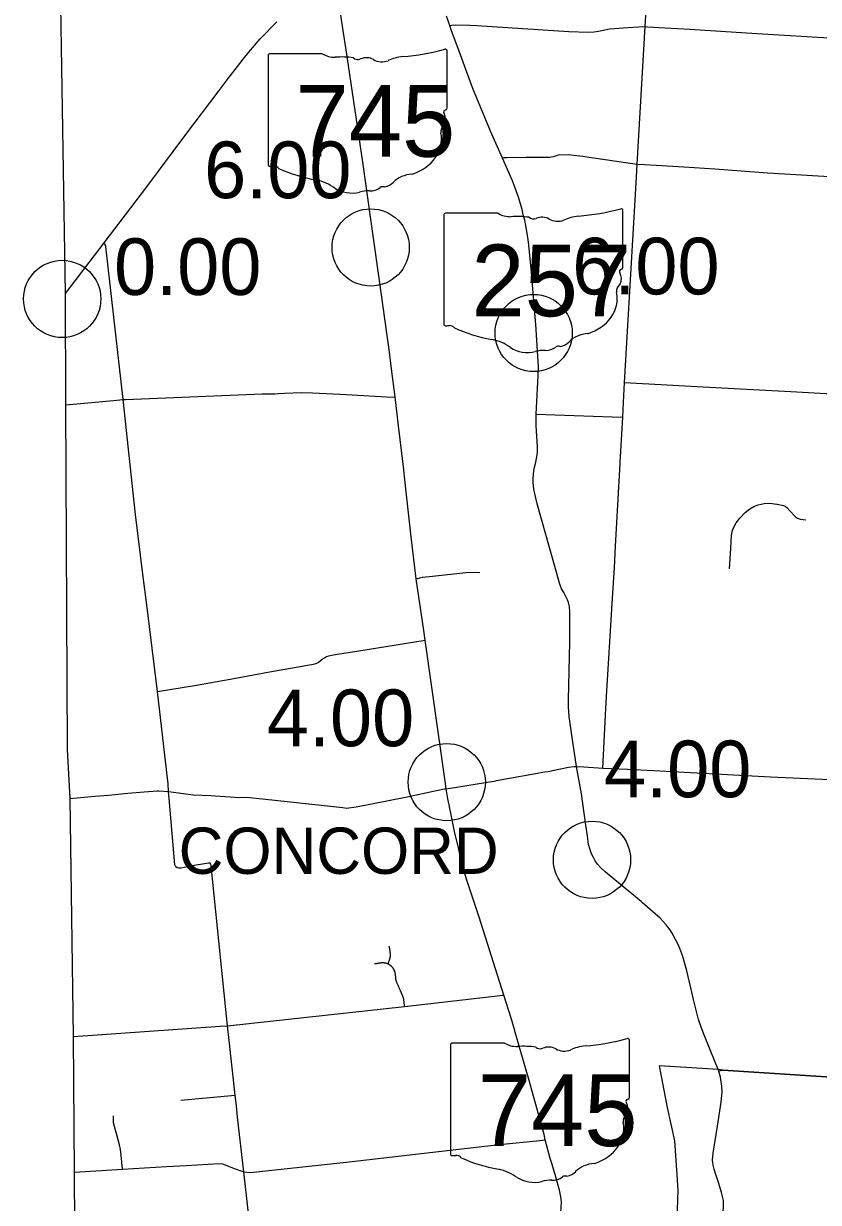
# Model space of a CAD drawing. Extents: x 1597222 to 1925846, y 496284 to 911751.
# Drawn here: x 1780072 to 1795517, y 792512 to 815408 of the extents above; entities that cross this region are included whole.
import ezdxf

# ---------------------------------------------------------------- set-up
doc = ezdxf.new("R2010")
doc.units = 0
for name, color, linetype in [('Default', 7, 'Continuous'), ('GM_X_County', 7, 'Continuous'), ('GM_X_County_Road', 7, 'Continuous'), ('GM_X_State_Route', 7, 'Continuous'), ('GM_X_State_Shield', 7, 'Continuous'), ('GM_X_Township', 7, 'Continuous'), ('GM_X_Township_Road', 7, 'Continuous'), ('GM_X_Township_Text', 7, 'Continuous'), ('GM_X_US_Route', 7, 'Continuous')]:
    doc.layers.add(name, color=color, linetype=linetype)

msp = doc.modelspace()

# ---------------------------------------------------------------- linework, layer by layer
at = {"layer": 'Default'}
for centre in [(1786817, 811060), (1780822, 810060), (1780822, 810060), (1789983, 809398), (1788295, 800675), (1791118, 799166)]:
    msp.add_circle(centre, 750, dxfattribs=at)
at = {"layer": 'GM_X_County'}
msp.add_lwpolyline([(1781083, 789921), (1781062, 793102), (1781040, 795733), (1780979, 800357), (1780927, 801312), (1780895, 808002), (1780889, 810163), (1780755, 818148)], dxfattribs=at)
at = {"layer": 'GM_X_County_Road'}
for points in [[(1791713, 807764), (1791713, 807764), (1791727, 808049), (1791747, 808435), (1791981, 812422), (1791996, 812680), (1792152, 815352), (1792421, 819851), (1792558, 822011)], [(1782890, 800490), (1782881, 800644), (1782856, 800863), (1782676, 802437), (1782464, 804119), (1782395, 804661), (1782246, 805871), (1782006, 808105), (1781669, 811078), (1781659, 811109), (1781650, 811131), (1781636, 811151)], [(1780895, 808002), (1781819, 808088), (1782006, 808105), (1782052, 808109), (1784707, 808216), (1784962, 808220), (1785026, 808223), (1785143, 808231), (1785474, 808240), (1785685, 808234), (1786347, 808204), (1787231, 808155), (1787289, 808159)], [(1791747, 808435), (1793395, 808348), (1794980, 808260), (1797031, 808146), (1797107, 808141), (1797153, 808138)], [(1790033, 807825), (1791509, 807773), (1791713, 807764)], [(1791328, 800949), (1791359, 801588), (1791381, 801980), (1791400, 802336), (1791517, 804248), (1791555, 804839), (1791576, 805255), (1791663, 806861), (1791666, 806898), (1791673, 806996), (1791713, 807764)], [(1790259, 800884), (1790662, 800965), (1790767, 800980), (1790816, 800981)], [(1790816, 800981), (1790957, 800973), (1791328, 800949), (1791805, 800926), (1792317, 800900), (1794586, 800781), (1795455, 800738), (1796520, 800687)], [(1788284, 800545), (1789248, 800701)], [(1789248, 800701), (1789260, 800704), (1790202, 800872), (1790259, 800884)], [(1780979, 800357), (1781251, 800385), (1781456, 800401), (1781721, 800423), (1782095, 800460), (1782415, 800484), (1782676, 800509), (1782703, 800508), (1782890, 800490), (1783080, 800464), (1783370, 800430), (1783710, 800417), (1784177, 800386), (1784465, 800376), (1784774, 800347), (1786277, 800180), (1786348, 800171), (1786537, 800193), (1787491, 800386), (1788093, 800511), (1788252, 800542), (1788284, 800545)], [(1784231, 794169), (1784213, 794320), (1784208, 794381), (1784184, 794592), (1784065, 795658), (1784036, 795945), (1783745, 798796), (1783719, 799058), (1783710, 799082), (1783697, 799100), (1783664, 799103), (1783307, 799040), (1783135, 799003), (1783086, 799003), (1783057, 799012), (1783029, 799032), (1783012, 799071), (1782957, 799680), (1782900, 800360), (1782890, 800490)], [(1784354, 793107), (1784231, 794169)]]:
    msp.add_lwpolyline(points, dxfattribs=at)
at = {"layer": 'GM_X_State_Route'}
for points in [[(1790208, 793730), (1790185, 793831), (1789883, 794924), (1789691, 795593), (1789552, 796074), (1789406, 796539), (1788925, 798054), (1788685, 798770), (1788593, 799061), (1788574, 799137), (1788559, 799211), (1788513, 799432), (1788454, 799683), (1788376, 800070), (1788357, 800160), (1788339, 800233), (1788316, 800352), (1788284, 800545), (1788263, 800693), (1787872, 803431), (1787846, 803622), (1787700, 804624), (1787601, 805437), (1787484, 806491), (1787451, 806800), (1787357, 807594), (1787289, 808159), (1787220, 808700), (1787174, 809078), (1787137, 809350), (1786980, 810466), (1786873, 811238), (1786667, 812717), (1786361, 814768), (1786233, 815611)], [(1789933, 810648), (1789882, 811163), (1789857, 811335), (1789809, 811591), (1789782, 811691), (1789760, 811794), (1789687, 812036), (1789570, 812353), (1789380, 812793), (1789145, 813319), (1788800, 814150), (1788666, 814519), (1788535, 814873), (1788387, 815268), (1788352, 815370), (1788288, 815554)], [(1789995, 809943), (1789934, 810642), (1789933, 810648)], [(1790677, 804093), (1790675, 804108), (1790660, 804164), (1790640, 804215), (1790609, 804281), (1790568, 804355), (1790526, 804429), (1790485, 804541), (1790432, 804726), (1790051, 806083), (1789985, 806362), (1789973, 806499), (1789971, 806567), (1789977, 806663), (1789996, 806768), (1790026, 806892), (1790053, 807030), (1790058, 807087), (1790058, 807184), (1790033, 807604), (1790033, 807825), (1790068, 808566), (1790079, 808738), (1790028, 809565), (1789995, 809943)], [(1790684, 803416), (1790687, 803933), (1790683, 804011), (1790681, 804061), (1790677, 804093)], [(1790816, 800981), (1790725, 801587), (1790674, 801951), (1790662, 802137), (1790662, 802272), (1790684, 803396), (1790684, 803416)], [(1792099, 798333), (1792069, 798359), (1791739, 798628), (1791453, 798865), (1791371, 798933), (1791282, 799017), (1791224, 799083), (1791180, 799145), (1791143, 799214), (1791110, 799281), (1791078, 799363), (1791051, 799466), (1791032, 799632), (1791000, 799840), (1790910, 800451), (1790816, 800981)], [(1793626, 794462), (1793626, 794462), (1793641, 794594), (1793644, 794648), (1793641, 794771), (1793623, 794897), (1793613, 794945), (1793580, 795059), (1793566, 795094), (1793498, 795270), (1793303, 795745), (1793237, 795913), (1793188, 796062), (1793091, 796453), (1793034, 796681), (1792957, 797013), (1792916, 797174), (1792881, 797288), (1792802, 797495), (1792672, 797742), (1792629, 797811), (1792556, 797903), (1792444, 798033), (1792099, 798333)], [(1793540, 791608), (1793549, 791942), (1793553, 792041), (1793562, 792113), (1793568, 792137), (1793585, 792183), (1793636, 792281), (1793653, 792321), (1793664, 792356), (1793672, 792401), (1793674, 792449), (1793673, 792501), (1793669, 792548), (1793654, 792626), (1793633, 792702), (1793579, 792877), (1793527, 793036), (1793489, 793158), (1793469, 793235), (1793462, 793288), (1793461, 793331), (1793468, 793471), (1793556, 793991), (1793626, 794462)], [(1790307, 793367), (1790208, 793730)], [(1790432, 790335), (1790390, 790706), (1790390, 790920), (1790399, 791128), (1790496, 792123), (1790514, 792320), (1790520, 792424), (1790521, 792501), (1790516, 792584), (1790507, 792652), (1790487, 792748), (1790462, 792838), (1790399, 793056), (1790334, 793268), (1790307, 793367)]]:
    msp.add_lwpolyline(points, dxfattribs=at)
at = {"layer": 'GM_X_State_Shield'}
for p, q in [((1788303, 813769), (1788303, 814875)), ((1788303, 813769), (1788303, 814875)), ((1784823, 814786), (1784823, 812673)), ((1784823, 814786), (1784823, 812673)), ((1785876, 814822), (1784857, 814822)), ((1785876, 814822), (1784857, 814822)), ((1788303, 813769), (1788303, 813769)), ((1788303, 813769), (1788303, 813769)), ((1788237, 811688), (1788237, 809575)), ((1788237, 811688), (1788237, 809575)), ((1789291, 811725), (1788271, 811725)), ((1789291, 811725), (1788271, 811725)), ((1791717, 810671), (1791717, 811777)), ((1791717, 810671), (1791717, 811777)), ((1791717, 810672), (1791717, 810671)), ((1791717, 810672), (1791717, 810671)), ((1791845, 794554), (1791845, 795660)), ((1791845, 794554), (1791845, 795660)), ((1788365, 795571), (1788365, 793458)), ((1788365, 795571), (1788365, 793458)), ((1789418, 795607), (1788399, 795607)), ((1789418, 795607), (1788399, 795607)), ((1791845, 794555), (1791845, 794554)), ((1791845, 794555), (1791845, 794554))]:
    msp.add_line(p, q, dxfattribs=at)
for centre, major_axis, start_param, end_param in [((1787063, 817703), (3691, 0), 4.814394, 5.042369), ((1787063, 817703), (3691, 0), 4.814394, 5.042369), ((1788264, 814879), (38.7, 0), 6.141152, 7.989035), ((1788264, 814879), (38.7, 0), 6.141152, 7.989035), ((1784863, 814790), (40.3, 0), 1.712693, 3.28349), ((1784863, 814790), (40.3, 0), 1.712693, 3.28349), ((1786119, 815068), (391, 0), 4.042523, 4.731795), ((1786119, 815068), (391, 0), 4.042523, 4.731795), ((1786249, 813636), (1404, 0), 1.404758, 1.657858), ((1786249, 813636), (1404, 0), 1.404758, 1.657858), ((1786567, 814801), (113, 0), 3.836095, 5.185415), ((1786567, 814801), (113, 0), 3.836095, 5.185415), ((1786733, 814557), (235, 0), 0.950623, 2.079405), ((1786733, 814557), (235, 0), 0.950623, 2.079405), ((1787036, 814892), (282, 0), 4.081561, 5.145723), ((1787036, 814892), (282, 0), 4.081561, 5.145723), ((1787534, 814177), (743, 0), 1.699011, 2.107814), ((1787534, 814177), (743, 0), 1.699011, 2.107814), ((1788294, 813688), (60, 0), 1.883978, 3.671073), ((1788294, 813688), (60, 0), 1.883978, 3.671073), ((1788262, 813765), (41.5, 0), 5.05454, 6.418171), ((1788262, 813765), (41.5, 0), 5.05454, 6.418171), ((1787913, 813548), (360, 0), 5.934695, 6.695948), ((1787913, 813548), (360, 0), 5.934695, 6.695948), ((1787270, 813166), (923, 0), 5.101752, 6.440018), ((1787270, 813166), (923, 0), 5.101752, 6.440018), ((1788442, 813306), (262, 0), 2.387724, 3.262537), ((1788442, 813306), (262, 0), 2.387724, 3.262537), ((1784863, 812668), (40.7, 0), 3.00124, 4.508301), ((1784863, 812668), (40.7, 0), 3.00124, 4.508301), ((1784869, 812884), (310, 0), 4.665946, 4.897461), ((1784869, 812884), (310, 0), 4.665946, 4.897461), ((1784933, 812551), (112, 0), 0.519207, 1.627899), ((1784933, 812551), (112, 0), 0.519207, 1.627899), ((1786346, 814449), (2665, 0), 4.195997, 4.488961), ((1786346, 814449), (2665, 0), 4.195997, 4.488961), ((1785551, 811723), (834, 0), 0.823519, 1.323587), ((1785551, 811723), (834, 0), 0.823519, 1.323587), ((1787659, 812079), (506, 0), 1.647645, 2.488434), ((1787659, 812079), (506, 0), 1.647645, 2.488434), ((1786453, 812540), (529, 0), 4.026481, 4.996735), ((1786453, 812540), (529, 0), 4.026481, 4.996735), ((1786759, 811810), (435, 0), 1.495662, 1.94098), ((1786759, 811810), (435, 0), 1.495662, 1.94098), ((1786797, 812382), (282, 0), 4.691044, 5.507374), ((1786797, 812382), (282, 0), 4.691044, 5.507374), ((1787053, 812177), (79.4, 0), 1.147584, 2.315152), ((1787053, 812177), (79.4, 0), 1.147584, 2.315152), ((1787019, 812468), (298, 0), 4.937069, 5.64225), ((1787019, 812468), (298, 0), 4.937069, 5.64225), ((1788277, 811693), (40.3, 0), 1.712693, 3.28349), ((1788277, 811693), (40.3, 0), 1.712693, 3.28349), ((1789533, 811970), (391, 0), 4.042523, 4.731795), ((1789533, 811970), (391, 0), 4.042523, 4.731795), ((1789663, 810538), (1404, 0), 1.404758, 1.657858), ((1789663, 810538), (1404, 0), 1.404758, 1.657858), ((1790948, 811079), (743, 0), 1.699011, 2.107814), ((1790948, 811079), (743, 0), 1.699011, 2.107814), ((1790478, 814606), (3691, 0), 4.814394, 5.042369), ((1790478, 814606), (3691, 0), 4.814394, 5.042369), ((1791679, 811782), (38.7, 0), 6.141152, 7.989035), ((1791679, 811782), (38.7, 0), 6.141152, 7.989035), ((1789982, 811704), (113, 0), 3.836095, 5.185415), ((1789982, 811704), (113, 0), 3.836095, 5.185415), ((1790147, 811459), (235, 0), 0.950623, 2.079405), ((1790147, 811459), (235, 0), 0.950623, 2.079405), ((1790450, 811794), (282, 0), 4.081561, 5.145723), ((1790450, 811794), (282, 0), 4.081561, 5.145723), ((1791708, 810590), (60, 0), 1.883978, 3.671073), ((1791708, 810590), (60, 0), 1.883978, 3.671073), ((1791327, 810451), (360, 0), 5.934695, 6.695948), ((1791327, 810451), (360, 0), 5.934695, 6.695948), ((1791676, 810667), (41.5, 0), 5.05454, 6.418171), ((1791676, 810667), (41.5, 0), 5.05454, 6.418171), ((1791856, 810209), (262, 0), 2.387724, 3.262537), ((1791856, 810209), (262, 0), 2.387724, 3.262537), ((1790684, 810068), (923, 0), 5.101752, 6.440018), ((1790684, 810068), (923, 0), 5.101752, 6.440018), ((1788277, 809570), (40.7, 0), 3.00124, 4.508301), ((1788277, 809570), (40.7, 0), 3.00124, 4.508301), ((1788283, 809787), (310, 0), 4.665946, 4.897461), ((1788283, 809787), (310, 0), 4.665946, 4.897461), ((1788347, 809453), (112, 0), 0.519207, 1.627899), ((1788347, 809453), (112, 0), 0.519207, 1.627899), ((1789760, 811352), (2665, 0), 4.195997, 4.488961), ((1789760, 811352), (2665, 0), 4.195997, 4.488961), ((1791074, 808982), (506, 0), 1.647645, 2.488434), ((1791074, 808982), (506, 0), 1.647645, 2.488434), ((1788965, 808626), (834, 0), 0.823519, 1.323587), ((1788965, 808626), (834, 0), 0.823519, 1.323587), ((1790467, 809080), (79.4, 0), 1.147584, 2.315152), ((1790467, 809080), (79.4, 0), 1.147584, 2.315152), ((1790433, 809370), (298, 0), 4.937069, 5.64225), ((1790433, 809370), (298, 0), 4.937069, 5.64225), ((1789867, 809443), (529, 0), 4.026481, 4.996735), ((1789867, 809443), (529, 0), 4.026481, 4.996735), ((1790173, 808712), (435, 0), 1.495662, 1.94098), ((1790173, 808712), (435, 0), 1.495662, 1.94098), ((1790212, 809284), (282, 0), 4.691044, 5.507374), ((1790212, 809284), (282, 0), 4.691044, 5.507374), ((1790605, 798489), (3691, 0), 4.814394, 5.042369), ((1790605, 798489), (3691, 0), 4.814394, 5.042369), ((1791806, 795664), (38.7, 0), 6.141152, 7.989035), ((1791806, 795664), (38.7, 0), 6.141152, 7.989035), ((1788404, 795576), (40.3, 0), 1.712693, 3.28349), ((1788404, 795576), (40.3, 0), 1.712693, 3.28349), ((1789661, 795853), (391, 0), 4.042523, 4.731795), ((1789661, 795853), (391, 0), 4.042523, 4.731795), ((1789791, 794421), (1404, 0), 1.404758, 1.657858), ((1789791, 794421), (1404, 0), 1.404758, 1.657858), ((1790109, 795587), (113, 0), 3.836095, 5.185415), ((1790109, 795587), (113, 0), 3.836095, 5.185415), ((1790275, 795342), (235, 0), 0.950623, 2.079405), ((1790275, 795342), (235, 0), 0.950623, 2.079405), ((1790578, 795677), (282, 0), 4.081561, 5.145723), ((1790578, 795677), (282, 0), 4.081561, 5.145723), ((1791076, 794962), (743, 0), 1.699011, 2.107814), ((1791076, 794962), (743, 0), 1.699011, 2.107814), ((1791836, 794473), (60, 0), 1.883978, 3.671073), ((1791836, 794473), (60, 0), 1.883978, 3.671073), ((1791804, 794550), (41.5, 0), 5.05454, 6.418171), ((1791804, 794550), (41.5, 0), 5.05454, 6.418171), ((1791455, 794333), (360, 0), 5.934695, 6.695948), ((1791455, 794333), (360, 0), 5.934695, 6.695948), ((1790812, 793951), (923, 0), 5.101752, 6.440018), ((1790812, 793951), (923, 0), 5.101752, 6.440018), ((1791984, 794092), (262, 0), 2.387724, 3.262537), ((1791984, 794092), (262, 0), 2.387724, 3.262537), ((1788405, 793453), (40.7, 0), 3.00124, 4.508301), ((1788405, 793453), (40.7, 0), 3.00124, 4.508301), ((1788411, 793669), (310, 0), 4.665946, 4.897461), ((1788411, 793669), (310, 0), 4.665946, 4.897461), ((1788475, 793336), (112, 0), 0.519207, 1.627899), ((1788475, 793336), (112, 0), 0.519207, 1.627899), ((1789888, 795235), (2665, 0), 4.195997, 4.488961), ((1789888, 795235), (2665, 0), 4.195997, 4.488961), ((1789093, 792508), (834, 0), 0.823519, 1.323587), ((1789093, 792508), (834, 0), 0.823519, 1.323587), ((1791201, 792864), (506, 0), 1.647645, 2.488434), ((1791201, 792864), (506, 0), 1.647645, 2.488434), ((1789995, 793325), (529, 0), 4.026481, 4.996735), ((1789995, 793325), (529, 0), 4.026481, 4.996735), ((1790301, 792595), (435, 0), 1.495662, 1.94098), ((1790301, 792595), (435, 0), 1.495662, 1.94098), ((1790339, 793167), (282, 0), 4.691044, 5.507374), ((1790339, 793167), (282, 0), 4.691044, 5.507374), ((1790595, 792962), (79.4, 0), 1.147584, 2.315152), ((1790595, 792962), (79.4, 0), 1.147584, 2.315152), ((1790561, 793253), (298, 0), 4.937069, 5.64225), ((1790561, 793253), (298, 0), 4.937069, 5.64225)]:
    msp.add_ellipse(centre, major_axis=major_axis, ratio=0.8, start_param=start_param, end_param=end_param, dxfattribs=at)
at = {"layer": 'GM_X_Township'}
msp.add_lwpolyline([(1797746, 818394), (1797534, 815021), (1797366, 812352), (1797107, 808141), (1796898, 804715), (1796632, 800682), (1796269, 794910), (1793660, 795080), (1793566, 795094), (1792419, 795165), (1792576, 794356), (1792720, 793710), (1792764, 793045), (1792783, 792753), (1792702, 790313)], dxfattribs=at)
at = {"layer": 'GM_X_Township_Road'}
for points in [[(1788352, 815370), (1788390, 815380), (1788460, 815383), (1788748, 815375), (1788877, 815369), (1790669, 815254), (1791049, 815244), (1791157, 815250), (1791245, 815260), (1791457, 815304), (1791820, 815329), (1792020, 815342), (1792152, 815352)], [(1792152, 815352), (1792194, 815348), (1792538, 815327), (1793017, 815298), (1794320, 815218), (1795831, 815124), (1797378, 815030)], [(1789380, 812793), (1789410, 812804), (1789463, 812806), (1789834, 812813), (1790208, 812814), (1790288, 812815), (1790397, 812833), (1790463, 812859), (1790661, 812863), (1790931, 812830), (1791812, 812705), (1791996, 812680)], [(1791996, 812680), (1792135, 812671), (1792361, 812658), (1792900, 812626), (1793503, 812590), (1794528, 812511), (1796172, 812413), (1797338, 812354)], [(1793788, 804820), (1793812, 805216), (1793820, 805355), (1793827, 805457), (1793843, 805540), (1793869, 805616), (1793918, 805709), (1793990, 805801), (1794094, 805915), (1794181, 805983), (1794259, 806027), (1794348, 806060), (1794464, 806087), (1794571, 806092), (1794710, 806073), (1794716, 806071), (1794836, 806048), (1794873, 806032), (1794905, 806009), (1795045, 805852), (1795072, 805827), (1795107, 805803), (1795159, 805782), (1795219, 805773), (1795271, 805772)], [(1787700, 804624), (1787823, 804655), (1788019, 804676), (1788666, 804747), (1788824, 804753), (1788939, 804749)], [(1782676, 802437), (1783430, 802559), (1784155, 802688), (1784818, 802812), (1785735, 802974), (1785747, 802978), (1785772, 802987), (1785797, 802999), (1785838, 803032), (1785874, 803062), (1785916, 803092), (1785959, 803113), (1786003, 803125), (1786060, 803139), (1786163, 803159), (1786385, 803195), (1787872, 803431)], [(1787154, 797141), (1787157, 797150), (1787160, 797159), (1787163, 797168), (1787166, 797177), (1787169, 797185), (1787172, 797194), (1787175, 797203), (1787178, 797212), (1787181, 797221), (1787184, 797230), (1787187, 797238), (1787189, 797242), (1787190, 797247), (1787191, 797251), (1787192, 797255), (1787194, 797259), (1787195, 797263), (1787196, 797267), (1787196, 797272), (1787197, 797276), (1787198, 797280), (1787199, 797284), (1787199, 797288), (1787200, 797293), (1787200, 797297), (1787200, 797301), (1787201, 797306), (1787201, 797310), (1787201, 797314), (1787201, 797319), (1787201, 797323), (1787201, 797327), (1787201, 797331), (1787201, 797336), (1787200, 797340), (1787200, 797344), (1787199, 797349), (1787199, 797353), (1787198, 797357), (1787197, 797366), (1787196, 797376), (1787194, 797385), (1787193, 797395), (1787191, 797404), (1787190, 797413), (1787188, 797423), (1787187, 797432), (1787186, 797442), (1787184, 797451), (1787183, 797460), (1787181, 797470), (1787180, 797479), (1787178, 797489)], [(1787475, 796318), (1787474, 796328), (1787473, 796338), (1787472, 796348), (1787471, 796358), (1787469, 796367), (1787468, 796377), (1787467, 796387), (1787466, 796397), (1787465, 796406), (1787464, 796416), (1787463, 796426), (1787462, 796436), (1787461, 796445), (1787460, 796450), (1787460, 796454), (1787459, 796458), (1787458, 796462), (1787458, 796466), (1787457, 796470), (1787456, 796474), (1787455, 796479), (1787454, 796483), (1787453, 796487), (1787452, 796491), (1787450, 796495), (1787449, 796499), (1787448, 796503), (1787446, 796507), (1787445, 796511), (1787443, 796514), (1787441, 796518), (1787437, 796527), (1787433, 796536), (1787429, 796545), (1787425, 796555), (1787421, 796564), (1787418, 796573), (1787414, 796582), (1787410, 796591), (1787406, 796600), (1787402, 796609), (1787398, 796618), (1787394, 796627), (1787390, 796636), (1787386, 796645), (1787382, 796654), (1787378, 796663), (1787374, 796672), (1787370, 796681), (1787366, 796690), (1787362, 796699), (1787358, 796708), (1787354, 796717), (1787350, 796726), (1787346, 796735), (1787342, 796744), (1787338, 796753), (1787334, 796762), (1787330, 796772), (1787326, 796781), (1787325, 796784), (1787323, 796788), (1787322, 796792), (1787320, 796796), (1787319, 796800), (1787317, 796804), (1787316, 796808), (1787315, 796812), (1787314, 796816), (1787313, 796820), (1787312, 796824), (1787311, 796828), (1787310, 796832), (1787309, 796836), (1787309, 796840), (1787308, 796844), (1787307, 796848), (1787307, 796852), (1787306, 796857), (1787306, 796866), (1787305, 796875), (1787304, 796884), (1787303, 796893), (1787302, 796902), (1787301, 796911), (1787300, 796920), (1787299, 796930), (1787298, 796939), (1787298, 796943), (1787297, 796947), (1787297, 796952), (1787296, 796956), (1787295, 796960), (1787294, 796964), (1787294, 796969), (1787293, 796973), (1787292, 796977), (1787290, 796981), (1787289, 796986), (1787288, 796990), (1787287, 796994), (1787285, 796998), (1787284, 797002), (1787282, 797006), (1787280, 797010), (1787279, 797014), (1787277, 797018), (1787275, 797022), (1787273, 797026), (1787271, 797030), (1787269, 797034), (1787267, 797037), (1787266, 797039), (1787265, 797041), (1787263, 797045), (1787260, 797049), (1787258, 797052), (1787256, 797056), (1787253, 797059), (1787251, 797063), (1787248, 797066), (1787245, 797070), (1787243, 797073), (1787240, 797076), (1787237, 797080), (1787234, 797083), (1787231, 797086), (1787228, 797089), (1787225, 797092), (1787222, 797095), (1787219, 797098), (1787216, 797101), (1787212, 797104), (1787209, 797107), (1787206, 797110), (1787202, 797112), (1787199, 797115), (1787195, 797117), (1787192, 797120), (1787188, 797122), (1787184, 797125), (1787181, 797127), (1787177, 797129), (1787173, 797132), (1787169, 797134), (1787166, 797136), (1787162, 797138), (1787158, 797140), (1787154, 797141), (1787150, 797143), (1787146, 797145), (1787142, 797147), (1787138, 797148), (1787134, 797150), (1787130, 797151), (1787126, 797152), (1787122, 797154), (1787118, 797155), (1787114, 797156), (1787109, 797157), (1787105, 797158), (1787101, 797159), (1787097, 797160), (1787093, 797161), (1787088, 797161), (1787084, 797162), (1787080, 797162), (1787076, 797163), (1787071, 797163), (1787067, 797164), (1787063, 797164), (1787059, 797164), (1787054, 797164), (1787050, 797164), (1787046, 797164), (1787041, 797164), (1787037, 797164), (1787033, 797164), (1787029, 797163), (1787024, 797163), (1787020, 797163), (1787016, 797162), (1787012, 797161), (1787002, 797160), (1786993, 797159), (1786984, 797157), (1786974, 797156), (1786965, 797154), (1786956, 797153), (1786946, 797152), (1786937, 797150), (1786928, 797149), (1786918, 797147), (1786909, 797146), (1786900, 797145), (1786890, 797143)], [(1781040, 795733), (1783893, 795933), (1784036, 795945), (1787475, 796318), (1789335, 796532), (1789379, 796538), (1789406, 796539)], [(1793580, 795059), (1793615, 795073), (1793660, 795080), (1796269, 794910), (1796478, 794896)], [(1783128, 794500), (1784184, 794592)], [(1781996, 793155), (1781969, 793427), (1781956, 793540), (1781937, 793633), (1781911, 793728), (1781821, 794057), (1781818, 794111), (1781821, 794191)], [(1784293, 793126), (1784354, 793107), (1784475, 793093), (1785619, 793219), (1786396, 793298), (1788869, 793586), (1789322, 793635), (1790104, 793716), (1790208, 793730)], [(1781062, 793102), (1781996, 793155), (1782851, 793208), (1783230, 793226), (1783871, 793267), (1783940, 793261), (1784180, 793162), (1784293, 793126)], [(1784638, 790333), (1784509, 791619), (1784435, 792353), (1784354, 793107)]]:
    msp.add_lwpolyline(points, dxfattribs=at)
at = {"layer": 'GM_X_US_Route'}
msp.add_lwpolyline([(1780889, 810163), (1781636, 811151), (1782464, 812239), (1783225, 813253), (1783854, 814085), (1784048, 814342), (1784229, 814573), (1784341, 814717), (1784446, 814854), (1784670, 815110), (1784992, 815444)], dxfattribs=at)

# ---------------------------------------------------------------- texts
at = {"layer": 'Default'}
for s, p in [('6.00', (1783580, 812017)), ('0.00', (1781830, 810137)), ('6.00', (1790733, 810148)), ('4.00', (1784799, 801373)), ('4.00', (1791350, 800382))]:
    msp.add_text(s, height=1100, dxfattribs=at).set_placement(p)
at = {"layer": 'GM_X_State_Shield'}
for s, p in [('745', (1785354, 812822)), ('745', (1785354, 812822)), ('257', (1788773, 809724)), ('257', (1788773, 809724)), ('745', (1788896, 793607)), ('745', (1788896, 793607))]:
    msp.add_text(s, height=1392.2, dxfattribs=at).set_placement(p)
at = {"layer": 'GM_X_Township_Text'}
msp.add_text('CONCORD', height=900, rotation=0, dxfattribs=at).set_placement((1783085, 798893))

doc.saveas('drawing.dxf')
